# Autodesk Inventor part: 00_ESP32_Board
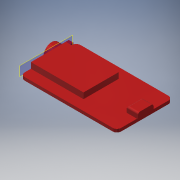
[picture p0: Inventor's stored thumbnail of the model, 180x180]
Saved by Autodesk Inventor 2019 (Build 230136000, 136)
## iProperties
Created: 2021-09
Part Number: 00_ESP32_Board
Material: Generisch
Document SubType Name: Modeling
Designer: Muriel
Density: 1 g/cm^3
Appearance: Hellrot
Author: Muriel
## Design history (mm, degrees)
sketch "Skizze1"
  geometry: L1 (-21.35, -13.5)-(21.35, -13.5); L2 (23.35, -11.5)-(23.35, 11.5); L3 (21.35, 13.5)-(-21.35, 13.5); L4 (-23.35, 11.5)-(-23.35, -11.5); L5 (-23.35, -13.5)-(23.35, 13.5); L6 (23.35, -13.5)-(-23.35, 13.5); A1 r 2 centre (21.35, 11.5) between (23.35, 11.5) and (21.35, 13.5); A2 r 2 centre (21.35, -11.5) between (21.35, -13.5) and (23.35, -11.5); A3 r 2 centre (-21.35, -11.5) between (-23.35, -11.5) and (-21.35, -13.5); A4 r 2 centre (-21.35, 11.5) between (-21.35, 13.5) and (-23.35, 11.5); 1 further point
  constraints: 12 end point, 8 point on circle, 8 point on line, 8 tangent, 4 centre point, 3 equal radius, 2 midpoint, 2 parallel, 1 horizontal, 1 perpendicular
  dimensions: "d0" = 46.7 distance of L6.end L5.end; "d1" = 27 distance of L5.end L6.start; "d2" = 2 radius of A1 (derived)
extrude "Extrusion1" new body sketch "Skizze1" distance "d3" = 1.5; taper "d4" = 0 deg
sketch "Skizze2"
  geometry: L1 (-21.35, -13.5)-(21.35, -13.5) reference; L2 (23.35, -11.5)-(23.35, 11.5) reference; L3 (21.35, 13.5)-(-21.35, 13.5) reference; L4 (-23.35, 11.5)-(-23.35, -11.5) reference; L5 (18.35, -3.75)-(23.85, -3.75); L6 (23.85, -3.75)-(23.85, 3.75); L7 (23.85, 3.75)-(18.35, 3.75); L8 (18.35, 3.75)-(18.35, -3.75); L9 (18.35, -3.75)-(23.85, 3.75); L10 (23.85, -3.75)-(18.35, 3.75); A1 r 2 centre (21.35, -11.5) between (21.35, -13.5) and (23.35, -11.5) reference; A2 r 2 centre (21.35, 11.5) between (23.35, 11.5) and (21.35, 13.5) reference; A3 r 2 centre (-21.35, 11.5) between (-21.35, 13.5) and (-23.35, 11.5) reference; A4 r 2 centre (-21.35, -11.5) between (-23.35, -11.5) and (-21.35, -13.5) reference; 2 further points
  constraints: 12 end point, 2 midpoint, 2 parallel, 1 horizontal, 1 perpendicular
  dimensions: "d5" = 5.5 distance of L7.end L6.end; "d6" = 7.5 distance of L6.end L5.end; "d7" = 0.5 distance between parallel lines of L6 L2
extrude "Extrusion2" join sketch "Skizze2" distance "d8" = 2.8; taper "d9" = 0 deg
fillet "Rundung1" dims "d10" = 1
sketch "Skizze3"
  geometry: L1 (-21.35, 13.5)-(21.35, 13.5) reference; L2 (-23.35, -11.5)-(-23.35, 11.5) reference; L3 (21.35, -13.5)-(-21.35, -13.5) reference; L4 (23.35, 11.5)-(23.35, -11.5) reference; L5 (2.15, -8.5)-(-23.35, -8.5); L6 (-23.35, -8.5)-(-23.35, 8.5); L7 (-23.35, 8.5)-(2.15, 8.5); L8 (2.15, 8.5)-(2.15, -8.5); L9 (2.15, -8.5)-(-23.35, 8.5); L10 (-23.35, -8.5)-(2.15, 8.5); A1 r 2 centre (-21.35, 11.5) between (-21.35, 13.5) and (-23.35, 11.5) reference; A2 r 2 centre (-21.35, -11.5) between (-23.35, -11.5) and (-21.35, -13.5) reference; A3 r 2 centre (21.35, -11.5) between (21.35, -13.5) and (23.35, -11.5) reference; A4 r 2 centre (21.35, 11.5) between (23.35, 11.5) and (21.35, 13.5) reference; 3 further points
  constraints: 12 end point, 4 midpoint, 2 parallel, 1 horizontal, 1 perpendicular
  dimensions: "d11" = 25.5 distance of L6.end L7.end; "d12" = 17 distance of L5.end L6.end
extrude "Extrusion3" join sketch "Skizze3" distance "d13" = 2.8; taper "d14" = 0 deg
sketch "Skizze5"
  geometry: L1 (-21.35, 13.5)-(21.35, 13.5) reference; L2 (-23.35, -11.5)-(-23.35, 11.5) reference; L3 (21.35, -13.5)-(-21.35, -13.5) reference; L4 (23.35, 11.5)-(23.35, -11.5) reference; L5 (-5.569, -8.25)-(-10.35, -8.25); L6 (-10.35, -8.25)-(-10.35, 8.25); L7 (-10.35, 8.25)-(-5.569, 8.25); L8 (-5.569, 8.25)-(-5.569, -8.25); L9 (-5.569, -8.25)-(-10.35, 8.25); L10 (-10.35, -8.25)-(-5.569, 8.25); L11 (15.35, -7.5)-(0.35, -7.5); L12 (0.35, -7.5)-(0.35, 7.5); L13 (0.35, 7.5)-(15.35, 7.5); L14 (15.35, 7.5)-(15.35, -7.5); L15 (15.35, -7.5)-(0.35, 7.5); L16 (0.35, -7.5)-(15.35, 7.5); A1 r 2 centre (-21.35, 11.5) between (-21.35, 13.5) and (-23.35, 11.5) reference; A2 r 2 centre (-21.35, -11.5) between (-23.35, -11.5) and (-21.35, -13.5) reference; A3 r 2 centre (21.35, -11.5) between (21.35, -13.5) and (23.35, -11.5) reference; A4 r 2 centre (21.35, 11.5) between (23.35, 11.5) and (21.35, 13.5) reference; 3 further points
  constraints: 24 end point, 4 midpoint, 4 parallel, 2 horizontal, 2 perpendicular
  dimensions: "d23" = 15 distance of L12.end L13.end; "d24" = 15 distance of L11.end L12.end; "d25" = 13 distance between parallel lines of L6 L2; "d26" = 16.5 distance between parallel lines of L5 L7; "d27" = 8 distance between parallel lines of L4 L14
extrude "Extrusion5" join sketch "Skizze5" distance "d28" = 2; taper "d29" = 0 deg
workplane "Arbeitsebene1"
sketch "Skizze8"
  geometry: L1 (7.5, 1.3)-(-1.5, 1.3); L2 (-1.5, 1.3)-(-1.5, -7.7); L3 (-1.5, -7.7)-(7.5, -7.7); L4 (7.5, -7.7)-(7.5, 1.3); L5 (7.5, 1.3)-(-1.5, -7.7); L6 (-1.5, 1.3)-(7.5, -7.7); L7 (0, 0)-(23, 0) reference; L8 (3, 4.3)-(20, 4.3) reference; L9 (19.75, -2)-(3.25, -2) reference; L10 (0, 0)-(-2, 0) reference; L11 (-2, 0)-(-2, 1.5) reference; 2 further points
  constraints: 12 end point, 2 midpoint, 2 parallel, 1 horizontal, 1 perpendicular
  dimensions: "d40" = 9 distance of L3.end L2.end; "d41" = 9 distance of L2.end L1.end; "d53" = 1.3 distance between parallel lines of L10 L1; "d54" = 0.5 distance between parallel lines of L2 L11
extrude "Extrusion8" join sketch "Skizze8" distance "d43" = 2.1; taper "d44" = 0 deg
sketch "Skizze9"
  geometry: L1 (7.5, 1.3)-(-1.5, 1.3) reference; L2 (-1.5, 1.3)-(-1.5, -7.7) reference; L3 (-1.5, -7.7)-(7.5, -7.7) reference; L4 (7.5, -7.7)-(7.5, 1.3) reference; C1 r 4 at (3, -3.2); 1 further point
  constraints: 1 centre point
  dimensions: "d45" = 8 diameter of C1; "d49" = 4.5 distance from line of C1.centre L1; "d50" = 4.5 distance from line of L4 C1.centre
extrude "Extrusion9" join sketch "Skizze9" distance "d46" = 3.8; taper "d47" = 0 deg
node "Volumenkörper1"
node "Projizierte Kontur1"
node "Projizierte Kontur2"
node "Projizierte Kontur4"
node "Projizierte Kontur8"
other parameters: "d39" = 1
